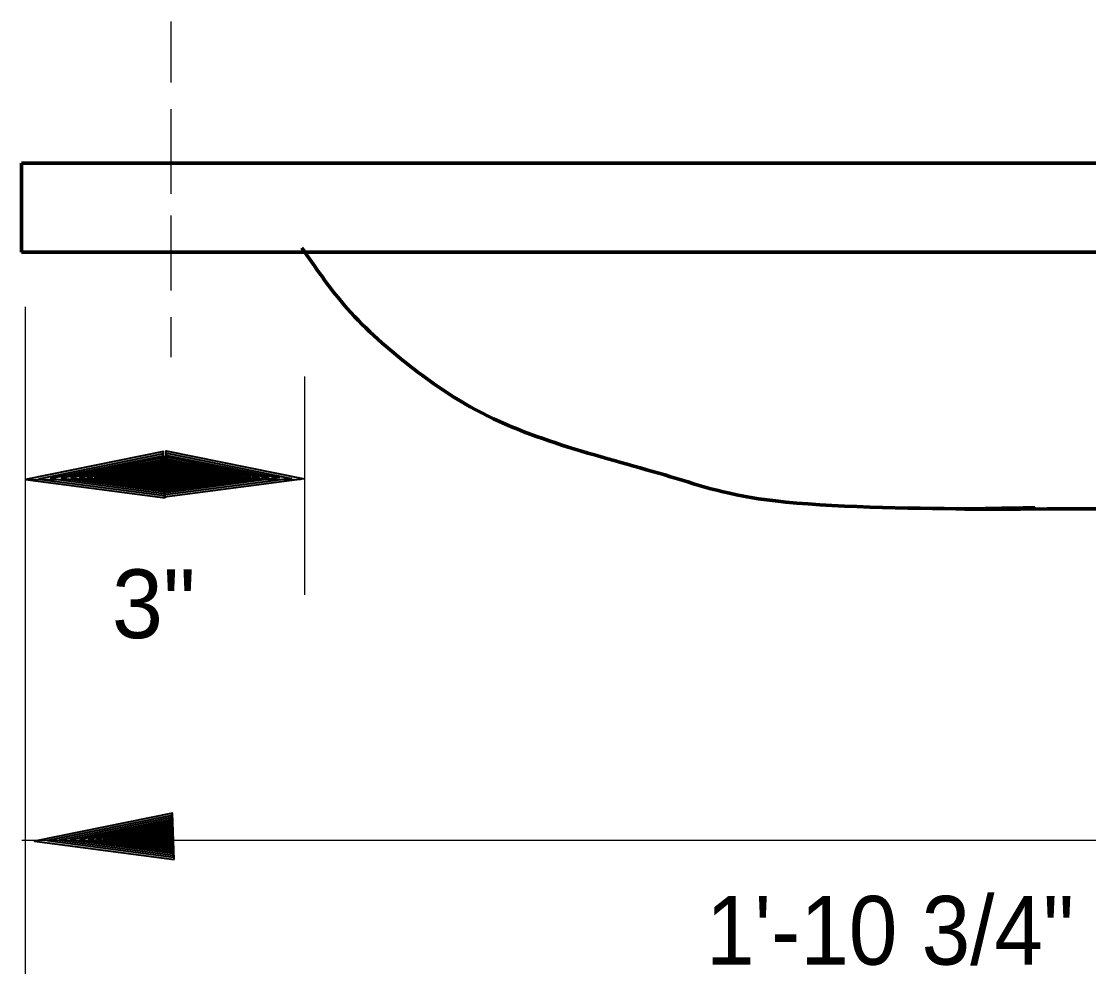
# Model space of a CAD drawing. Extents: x 895.6 to 930.4, y -2278.6 to -2254.7.
# Drawn here: x 915.213 to 917.21, y -2270.16 to -2268.392 of the extents above; entities that cross this region are included whole.
import ezdxf

# ---------------------------------------------------------------- set-up
doc = ezdxf.new("R2010")
doc.units = 0
doc.header["$LTSCALE"] = 0.051
doc.layers.add('1', color=7, linetype='Continuous', lineweight=70)
doc.layers.add('3', color=7, linetype='Continuous', lineweight=40)

msp = doc.modelspace()

# ---------------------------------------------------------------- hatches: boundary and pattern name
at = {"layer": '3'}
for points in [[(915.4825, -2269.28317), (915.47958, -2269.19642), (915.22108, -2269.24867), (915.22108, -2269.24867)], [(915.4815, -2269.28192), (915.48442, -2269.19525), (915.74292, -2269.24742), (915.74292, -2269.24742)], [(915.48125, -2269.27883), (915.4785, -2269.20083), (915.24592, -2269.24775), (915.24592, -2269.24775)], [(915.48, -2269.27492), (915.47758, -2269.20475), (915.26833, -2269.24708), (915.26833, -2269.24708)], [(915.479, -2269.27142), (915.47683, -2269.20842), (915.28833, -2269.24642), (915.28833, -2269.24642)], [(915.47808, -2269.26842), (915.47608, -2269.21158), (915.30642, -2269.24583), (915.30642, -2269.24583)], [(915.477, -2269.2655), (915.47533, -2269.21442), (915.32267, -2269.24525), (915.32267, -2269.24525)], [(915.48275, -2269.27758), (915.4855, -2269.19958), (915.71808, -2269.2465), (915.71808, -2269.2465)], [(915.484, -2269.27367), (915.48642, -2269.20358), (915.69567, -2269.24583), (915.69567, -2269.24583)], [(915.485, -2269.27025), (915.48717, -2269.20717), (915.67567, -2269.24517), (915.67567, -2269.24517)], [(915.48592, -2269.26725), (915.48792, -2269.21033), (915.65758, -2269.24458), (915.65758, -2269.24458)], [(915.487, -2269.26433), (915.48867, -2269.21325), (915.64133, -2269.24408), (915.64133, -2269.24408)], [(915.48767, -2269.26175), (915.48917, -2269.21575), (915.62667, -2269.2435), (915.62667, -2269.2435)], [(915.47633, -2269.263), (915.47483, -2269.217), (915.33733, -2269.24475), (915.33733, -2269.24475)], [(915.4755, -2269.26083), (915.47425, -2269.21933), (915.35067, -2269.24433), (915.35067, -2269.24433)], [(915.47508, -2269.25875), (915.47375, -2269.22133), (915.36242, -2269.24375), (915.36242, -2269.24375)], [(915.47433, -2269.25683), (915.47317, -2269.22317), (915.37325, -2269.2435), (915.37325, -2269.2435)], [(915.47383, -2269.25525), (915.47283, -2269.22492), (915.38283, -2269.24317), (915.38283, -2269.24317)], [(915.47342, -2269.25367), (915.47242, -2269.2265), (915.39142, -2269.24283), (915.39142, -2269.24283)], [(915.473, -2269.25242), (915.47217, -2269.22792), (915.39933, -2269.24258), (915.39933, -2269.24258)], [(915.47242, -2269.25117), (915.47192, -2269.22908), (915.40625, -2269.24233), (915.40625, -2269.24233)], [(915.47225, -2269.25008), (915.47158, -2269.23017), (915.4125, -2269.24217), (915.4125, -2269.24217)], [(915.47183, -2269.249), (915.47142, -2269.23117), (915.41817, -2269.24192), (915.41817, -2269.24192)], [(915.47158, -2269.24817), (915.47108, -2269.232), (915.42325, -2269.24167), (915.42325, -2269.24167)], [(915.4715, -2269.24733), (915.47092, -2269.23292), (915.42783, -2269.2415), (915.42783, -2269.2415)], [(915.47108, -2269.24683), (915.47083, -2269.23375), (915.43183, -2269.2415), (915.43183, -2269.2415)], [(915.47083, -2269.24625), (915.4705, -2269.2345), (915.43558, -2269.24142), (915.43558, -2269.24142)], [(915.47058, -2269.24583), (915.47017, -2269.23525), (915.43883, -2269.24158), (915.43883, -2269.24158)], [(915.47058, -2269.24517), (915.47017, -2269.23575), (915.44192, -2269.24142), (915.44192, -2269.24142)], [(915.47042, -2269.24467), (915.47008, -2269.23617), (915.44458, -2269.24125), (915.44458, -2269.24125)], [(915.4885, -2269.25958), (915.48975, -2269.21808), (915.61333, -2269.24308), (915.61333, -2269.24308)], [(915.48892, -2269.25758), (915.49025, -2269.22008), (915.60158, -2269.24258), (915.60158, -2269.24258)], [(915.48967, -2269.25558), (915.49083, -2269.22192), (915.59075, -2269.24225), (915.59075, -2269.24225)], [(915.49017, -2269.254), (915.49117, -2269.22375), (915.58117, -2269.24192), (915.58117, -2269.24192)], [(915.49058, -2269.25242), (915.49158, -2269.22533), (915.57258, -2269.24158), (915.57258, -2269.24158)], [(915.491, -2269.25117), (915.49183, -2269.22667), (915.56467, -2269.24133), (915.56467, -2269.24133)], [(915.49158, -2269.24992), (915.49208, -2269.22783), (915.55775, -2269.24108), (915.55775, -2269.24108)], [(915.49175, -2269.24883), (915.49242, -2269.229), (915.5515, -2269.241), (915.5515, -2269.241)], [(915.49217, -2269.24783), (915.49258, -2269.22992), (915.54583, -2269.24067), (915.54583, -2269.24067)], [(915.49242, -2269.24692), (915.49292, -2269.23075), (915.54075, -2269.24042), (915.54075, -2269.24042)], [(915.4925, -2269.24608), (915.49308, -2269.23167), (915.53617, -2269.24033), (915.53617, -2269.24033)], [(915.49292, -2269.24558), (915.49317, -2269.2325), (915.53217, -2269.24033), (915.53217, -2269.24033)], [(915.49317, -2269.245), (915.4935, -2269.23325), (915.52842, -2269.24025), (915.52842, -2269.24025)], [(915.49342, -2269.24458), (915.49383, -2269.234), (915.52517, -2269.24033), (915.52517, -2269.24033)], [(915.49342, -2269.244), (915.49383, -2269.2345), (915.52208, -2269.24025), (915.52208, -2269.24025)], [(915.49358, -2269.24342), (915.49392, -2269.235), (915.51942, -2269.24), (915.51942, -2269.24)], [(915.49383, -2269.24308), (915.494, -2269.2355), (915.517, -2269.24008), (915.517, -2269.24008)], [(915.47017, -2269.24433), (915.47, -2269.23675), (915.447, -2269.24133), (915.447, -2269.24133)], [(915.49925, -2269.9595), (915.49633, -2269.87283), (915.23792, -2269.925), (915.23792, -2269.925)], [(915.498, -2269.95517), (915.49525, -2269.87717), (915.26267, -2269.92417), (915.26267, -2269.92417)], [(915.49675, -2269.95125), (915.49442, -2269.88117), (915.28508, -2269.9235), (915.28508, -2269.9235)], [(915.49575, -2269.94783), (915.49358, -2269.88475), (915.30508, -2269.92275), (915.30508, -2269.92275)], [(915.49483, -2269.94483), (915.49292, -2269.888), (915.32317, -2269.92217), (915.32317, -2269.92217)], [(915.49375, -2269.94192), (915.49217, -2269.89083), (915.33942, -2269.92167), (915.33942, -2269.92167)], [(915.49308, -2269.93933), (915.49158, -2269.89342), (915.35417, -2269.92117), (915.35417, -2269.92117)], [(915.49225, -2269.93717), (915.491, -2269.89575), (915.36742, -2269.92067), (915.36742, -2269.92067)], [(915.49183, -2269.93517), (915.4905, -2269.89775), (915.37917, -2269.92017), (915.37917, -2269.92017)], [(915.49108, -2269.93325), (915.48992, -2269.8995), (915.39, -2269.91983), (915.39, -2269.91983)], [(915.49067, -2269.93167), (915.48958, -2269.90133), (915.39958, -2269.91958), (915.39958, -2269.91958)], [(915.49017, -2269.93008), (915.48917, -2269.90292), (915.40817, -2269.91917), (915.40817, -2269.91917)], [(915.48975, -2269.92875), (915.48892, -2269.90425), (915.41608, -2269.919), (915.41608, -2269.919)], [(915.48917, -2269.9275), (915.48867, -2269.9055), (915.423, -2269.91875), (915.423, -2269.91875)], [(915.489, -2269.9265), (915.48833, -2269.90658), (915.42925, -2269.91858), (915.42925, -2269.91858)], [(915.48858, -2269.92542), (915.48817, -2269.90758), (915.43492, -2269.91825), (915.43492, -2269.91825)], [(915.48842, -2269.9245), (915.48783, -2269.90842), (915.44, -2269.91808), (915.44, -2269.91808)], [(915.48825, -2269.92367), (915.48767, -2269.90925), (915.44458, -2269.91792), (915.44458, -2269.91792)], [(915.48783, -2269.92325), (915.48758, -2269.91008), (915.44867, -2269.91792), (915.44867, -2269.91792)], [(915.48767, -2269.92267), (915.48725, -2269.91083), (915.45233, -2269.91783), (915.45233, -2269.91783)], [(915.48733, -2269.92217), (915.48692, -2269.91158), (915.45558, -2269.918), (915.45558, -2269.918)], [(915.48733, -2269.92158), (915.48692, -2269.91217), (915.45867, -2269.91783), (915.45867, -2269.91783)], [(915.48717, -2269.92108), (915.48683, -2269.91258), (915.46142, -2269.91758), (915.46142, -2269.91758)], [(915.48692, -2269.92067), (915.48675, -2269.91308), (915.46375, -2269.91767), (915.46375, -2269.91767)]]:
    msp.add_hatch(color=256, dxfattribs=at).paths.add_polyline_path(points)

# ---------------------------------------------------------------- linework, layer by layer
at = {"layer": '1', "lineweight": 25}
for p, q in [((915.49358, -2268.50617), (915.49358, -2268.39175)), ((915.49358, -2268.71433), (915.49358, -2268.55592)), ((915.49358, -2268.89533), (915.49358, -2268.755)), ((915.22142, -2270.94408), (915.22142, -2268.92592)), ((915.49358, -2269.02017), (915.49358, -2268.94508)), ((915.74392, -2269.46433), (915.74392, -2269.05583)), ((915.22358, -2269.24875), (915.73583, -2269.24875)), ((915.21425, -2269.9235), (919.14633, -2269.9235))]:
    msp.add_line(p, q, dxfattribs=at)
at = {"layer": '1'}
for p, q in [((919.152, -2268.65675), (915.21342, -2268.65675)), ((915.21342, -2268.65675), (915.21342, -2268.82342)), ((919.152, -2268.82342), (915.21342, -2268.82342))]:
    msp.add_line(p, q, dxfattribs=at)
msp.add_spline([(919.152, -2269.30267), (917.08242, -2269.30392), (916.97917, -2269.30392), (917.07483, -2269.302), (916.62433, -2269.28875), (916.428, -2269.24342), (916.23667, -2269.188), (916.05308, -2269.11258), (915.93467, -2269.03183), (915.81633, -2268.921), (915.73833, -2268.81525)], degree=3, dxfattribs=at)
at = {"layer": '3'}
for points in [[(915.4825, -2269.28317), (915.47958, -2269.19642), (915.22108, -2269.24867), (915.22108, -2269.24867)], [(915.4815, -2269.28192), (915.48442, -2269.19525), (915.74292, -2269.24742), (915.74292, -2269.24742)], [(915.48125, -2269.27883), (915.4785, -2269.20083), (915.24592, -2269.24775), (915.24592, -2269.24775)], [(915.48, -2269.27492), (915.47758, -2269.20475), (915.26833, -2269.24708), (915.26833, -2269.24708)], [(915.479, -2269.27142), (915.47683, -2269.20842), (915.28833, -2269.24642), (915.28833, -2269.24642)], [(915.47808, -2269.26842), (915.47608, -2269.21158), (915.30642, -2269.24583), (915.30642, -2269.24583)], [(915.477, -2269.2655), (915.47533, -2269.21442), (915.32267, -2269.24525), (915.32267, -2269.24525)], [(915.48275, -2269.27758), (915.4855, -2269.19958), (915.71808, -2269.2465), (915.71808, -2269.2465)], [(915.484, -2269.27367), (915.48642, -2269.20358), (915.69567, -2269.24583), (915.69567, -2269.24583)], [(915.485, -2269.27025), (915.48717, -2269.20717), (915.67567, -2269.24517), (915.67567, -2269.24517)], [(915.48592, -2269.26725), (915.48792, -2269.21033), (915.65758, -2269.24458), (915.65758, -2269.24458)], [(915.487, -2269.26433), (915.48867, -2269.21325), (915.64133, -2269.24408), (915.64133, -2269.24408)], [(915.48767, -2269.26175), (915.48917, -2269.21575), (915.62667, -2269.2435), (915.62667, -2269.2435)], [(915.47633, -2269.263), (915.47483, -2269.217), (915.33733, -2269.24475), (915.33733, -2269.24475)], [(915.4755, -2269.26083), (915.47425, -2269.21933), (915.35067, -2269.24433), (915.35067, -2269.24433)], [(915.47508, -2269.25875), (915.47375, -2269.22133), (915.36242, -2269.24375), (915.36242, -2269.24375)], [(915.47433, -2269.25683), (915.47317, -2269.22317), (915.37325, -2269.2435), (915.37325, -2269.2435)], [(915.47383, -2269.25525), (915.47283, -2269.22492), (915.38283, -2269.24317), (915.38283, -2269.24317)], [(915.47342, -2269.25367), (915.47242, -2269.2265), (915.39142, -2269.24283), (915.39142, -2269.24283)], [(915.473, -2269.25242), (915.47217, -2269.22792), (915.39933, -2269.24258), (915.39933, -2269.24258)], [(915.47242, -2269.25117), (915.47192, -2269.22908), (915.40625, -2269.24233), (915.40625, -2269.24233)], [(915.47225, -2269.25008), (915.47158, -2269.23017), (915.4125, -2269.24217), (915.4125, -2269.24217)], [(915.47183, -2269.249), (915.47142, -2269.23117), (915.41817, -2269.24192), (915.41817, -2269.24192)], [(915.47158, -2269.24817), (915.47108, -2269.232), (915.42325, -2269.24167), (915.42325, -2269.24167)], [(915.4715, -2269.24733), (915.47092, -2269.23292), (915.42783, -2269.2415), (915.42783, -2269.2415)], [(915.47108, -2269.24683), (915.47083, -2269.23375), (915.43183, -2269.2415), (915.43183, -2269.2415)], [(915.47083, -2269.24625), (915.4705, -2269.2345), (915.43558, -2269.24142), (915.43558, -2269.24142)], [(915.47058, -2269.24583), (915.47017, -2269.23525), (915.43883, -2269.24158), (915.43883, -2269.24158)], [(915.47058, -2269.24517), (915.47017, -2269.23575), (915.44192, -2269.24142), (915.44192, -2269.24142)], [(915.47042, -2269.24467), (915.47008, -2269.23617), (915.44458, -2269.24125), (915.44458, -2269.24125)], [(915.4885, -2269.25958), (915.48975, -2269.21808), (915.61333, -2269.24308), (915.61333, -2269.24308)], [(915.48892, -2269.25758), (915.49025, -2269.22008), (915.60158, -2269.24258), (915.60158, -2269.24258)], [(915.48967, -2269.25558), (915.49083, -2269.22192), (915.59075, -2269.24225), (915.59075, -2269.24225)], [(915.49017, -2269.254), (915.49117, -2269.22375), (915.58117, -2269.24192), (915.58117, -2269.24192)], [(915.49058, -2269.25242), (915.49158, -2269.22533), (915.57258, -2269.24158), (915.57258, -2269.24158)], [(915.491, -2269.25117), (915.49183, -2269.22667), (915.56467, -2269.24133), (915.56467, -2269.24133)], [(915.49158, -2269.24992), (915.49208, -2269.22783), (915.55775, -2269.24108), (915.55775, -2269.24108)], [(915.49175, -2269.24883), (915.49242, -2269.229), (915.5515, -2269.241), (915.5515, -2269.241)], [(915.49217, -2269.24783), (915.49258, -2269.22992), (915.54583, -2269.24067), (915.54583, -2269.24067)], [(915.49242, -2269.24692), (915.49292, -2269.23075), (915.54075, -2269.24042), (915.54075, -2269.24042)], [(915.4925, -2269.24608), (915.49308, -2269.23167), (915.53617, -2269.24033), (915.53617, -2269.24033)], [(915.49292, -2269.24558), (915.49317, -2269.2325), (915.53217, -2269.24033), (915.53217, -2269.24033)], [(915.49317, -2269.245), (915.4935, -2269.23325), (915.52842, -2269.24025), (915.52842, -2269.24025)], [(915.49342, -2269.24458), (915.49383, -2269.234), (915.52517, -2269.24033), (915.52517, -2269.24033)], [(915.49342, -2269.244), (915.49383, -2269.2345), (915.52208, -2269.24025), (915.52208, -2269.24025)], [(915.49358, -2269.24342), (915.49392, -2269.235), (915.51942, -2269.24), (915.51942, -2269.24)], [(915.49383, -2269.24308), (915.494, -2269.2355), (915.517, -2269.24008), (915.517, -2269.24008)], [(915.47017, -2269.24433), (915.47, -2269.23675), (915.447, -2269.24133), (915.447, -2269.24133)], [(915.49925, -2269.9595), (915.49633, -2269.87283), (915.23792, -2269.925), (915.23792, -2269.925)], [(915.498, -2269.95517), (915.49525, -2269.87717), (915.26267, -2269.92417), (915.26267, -2269.92417)], [(915.49675, -2269.95125), (915.49442, -2269.88117), (915.28508, -2269.9235), (915.28508, -2269.9235)], [(915.49575, -2269.94783), (915.49358, -2269.88475), (915.30508, -2269.92275), (915.30508, -2269.92275)], [(915.49483, -2269.94483), (915.49292, -2269.888), (915.32317, -2269.92217), (915.32317, -2269.92217)], [(915.49375, -2269.94192), (915.49217, -2269.89083), (915.33942, -2269.92167), (915.33942, -2269.92167)], [(915.49308, -2269.93933), (915.49158, -2269.89342), (915.35417, -2269.92117), (915.35417, -2269.92117)], [(915.49225, -2269.93717), (915.491, -2269.89575), (915.36742, -2269.92067), (915.36742, -2269.92067)], [(915.49183, -2269.93517), (915.4905, -2269.89775), (915.37917, -2269.92017), (915.37917, -2269.92017)], [(915.49108, -2269.93325), (915.48992, -2269.8995), (915.39, -2269.91983), (915.39, -2269.91983)], [(915.49067, -2269.93167), (915.48958, -2269.90133), (915.39958, -2269.91958), (915.39958, -2269.91958)], [(915.49017, -2269.93008), (915.48917, -2269.90292), (915.40817, -2269.91917), (915.40817, -2269.91917)], [(915.48975, -2269.92875), (915.48892, -2269.90425), (915.41608, -2269.919), (915.41608, -2269.919)], [(915.48917, -2269.9275), (915.48867, -2269.9055), (915.423, -2269.91875), (915.423, -2269.91875)], [(915.489, -2269.9265), (915.48833, -2269.90658), (915.42925, -2269.91858), (915.42925, -2269.91858)], [(915.48858, -2269.92542), (915.48817, -2269.90758), (915.43492, -2269.91825), (915.43492, -2269.91825)], [(915.48842, -2269.9245), (915.48783, -2269.90842), (915.44, -2269.91808), (915.44, -2269.91808)], [(915.48825, -2269.92367), (915.48767, -2269.90925), (915.44458, -2269.91792), (915.44458, -2269.91792)], [(915.48783, -2269.92325), (915.48758, -2269.91008), (915.44867, -2269.91792), (915.44867, -2269.91792)], [(915.48767, -2269.92267), (915.48725, -2269.91083), (915.45233, -2269.91783), (915.45233, -2269.91783)], [(915.48733, -2269.92217), (915.48692, -2269.91158), (915.45558, -2269.918), (915.45558, -2269.918)], [(915.48733, -2269.92158), (915.48692, -2269.91217), (915.45867, -2269.91783), (915.45867, -2269.91783)], [(915.48717, -2269.92108), (915.48683, -2269.91258), (915.46142, -2269.91758), (915.46142, -2269.91758)], [(915.48692, -2269.92067), (915.48675, -2269.91308), (915.46375, -2269.91767), (915.46375, -2269.91767)]]:
    msp.add_lwpolyline(points, close=True, dxfattribs=at)

# ---------------------------------------------------------------- texts
at = {"layer": '1'}
msp.add_text('3"', height=0.1286, dxfattribs=at).set_placement((915.38283, -2269.54542))
at = {"layer": '1', "width": 0.95}
msp.add_text('1\'-10 3/4"', height=0.1286, dxfattribs=at).set_placement((916.49417, -2270.15617))

doc.saveas('drawing.dxf')
